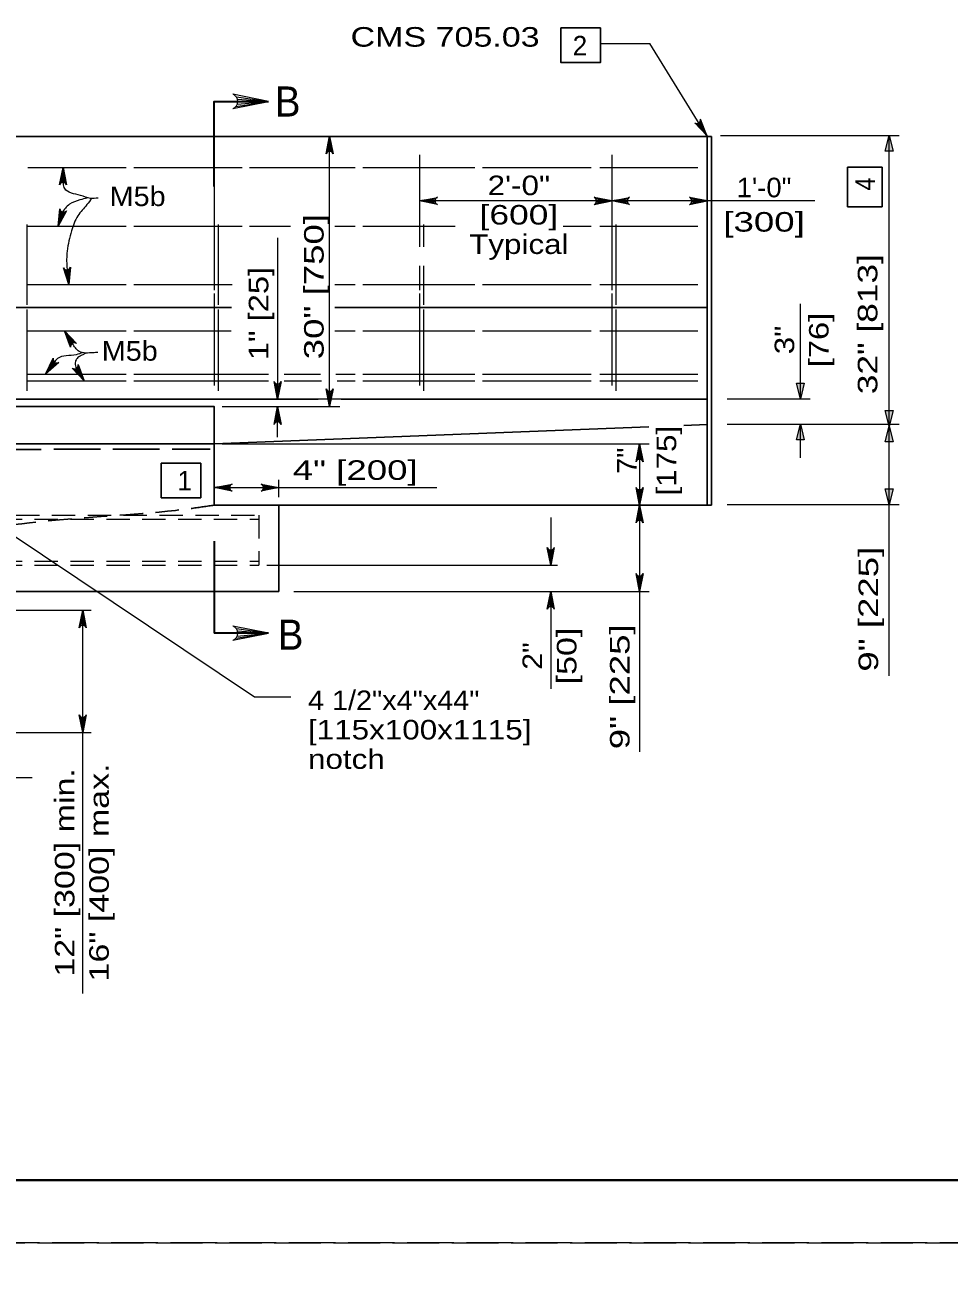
# Model space of a CAD drawing. Extents: x 1083.1 to 1123, y 697.4 to 741.4.
# Drawn here: x 1096.71 to 1104.08, y 719.1 to 729.07 of the extents above; entities that cross this region are included whole.
import ezdxf
from ezdxf.enums import TextEntityAlignment as Align

# ---------------------------------------------------------------- set-up
doc = ezdxf.new("R2010")
doc.units = 0
doc.header["$LTSCALE"] = 0.062
doc.linetypes.add('LONG_DASHED', pattern=[7.5, 6, -1.5])
doc.linetypes.add('MEDIUM_DASHED', pattern=[4.5, 3, -1.5])
doc.layers.add('1', color=7, linetype='Continuous', lineweight=13)

msp = doc.modelspace()

# ---------------------------------------------------------------- hatches: boundary and pattern name
at = {"layer": '1'}
for points in [[(1103.57467, 728.06383), (1103.60592, 728.18875), (1103.63717, 728.06383)], [(1102.92917, 726.21258), (1102.89792, 726.08758), (1102.86667, 726.21258)], [(1103.63717, 725.99342), (1103.60592, 725.8685), (1103.57467, 725.99342)], [(1102.86667, 725.76058), (1102.89792, 725.8855), (1102.92917, 725.76058)], [(1103.57467, 725.74358), (1103.60592, 725.8685), (1103.63717, 725.74358)], [(1103.63717, 725.36825), (1103.60592, 725.24333), (1103.57467, 725.36825)]]:
    msp.add_hatch(color=256, dxfattribs=at).paths.add_polyline_path(points)

# ---------------------------------------------------------------- linework, layer by layer
for p, q in [((1101.30292, 728.92225), (1101.69808, 728.92225)), ((1102.15483, 728.182), (1101.69808, 728.92225)), ((1098.4, 728.49667), (1098.65642, 728.46083)), ((1098.40867, 728.47892), (1098.65642, 728.46083)), ((1098.397, 728.42117), (1098.65642, 728.46083)), ((1098.40683, 728.43775), (1098.65642, 728.46083)), ((1098.41133, 728.46083), (1098.65642, 728.46083)), ((1102.06858, 728.2845), (1102.15267, 728.18875)), ((1102.078, 728.28475), (1102.15267, 728.18875)), ((1102.08858, 728.28892), (1102.15267, 728.18875)), ((1102.09533, 728.29475), (1102.15267, 728.18875)), ((1102.10033, 728.30292), (1102.15267, 728.18875)), ((1099.12417, 728.05458), (1099.144, 728.18433)), ((1099.1325, 728.0595), (1099.144, 728.18433)), ((1099.144, 726.02625), (1099.144, 728.18433)), ((1099.144, 728.06175), (1099.144, 728.18433)), ((1099.15308, 728.06042), (1099.144, 728.18433)), ((1099.16192, 728.05608), (1099.144, 728.18433)), ((1102.14325, 728.181), (1102.172, 728.181)), ((1102.172, 728.181), (1102.14325, 728.181)), ((1102.25975, 728.18875), (1103.68458, 728.18875)), ((1103.60592, 723.87792), (1103.60592, 728.18875)), ((1098.22375, 728.03392), (1098.22375, 726.95475)), ((1099.86175, 728.03392), (1099.86175, 727.29925)), ((1101.39433, 728.03392), (1101.39433, 726.95475)), ((1096.73733, 727.93217), (1097.52033, 727.93217)), ((1096.998, 727.80675), (1097.02008, 727.93217)), ((1097.00625, 727.81133), (1097.02008, 727.93217)), ((1097.01742, 727.81333), (1097.02008, 727.93217)), ((1097.02625, 727.81183), (1097.02008, 727.93217)), ((1097.03475, 727.80733), (1097.02008, 727.93217)), ((1097.58367, 727.93217), (1098.44517, 727.93217)), ((1098.50367, 727.93217), (1099.34775, 727.93217)), ((1099.40783, 727.93217), (1100.301, 727.93217)), ((1100.36275, 727.93217), (1101.22967, 727.93217)), ((1101.29775, 727.93217), (1102.07925, 727.93217)), ((1099.98992, 727.68508), (1099.86175, 727.66708)), ((1099.98558, 727.67617), (1099.86175, 727.66708)), ((1099.98425, 727.66708), (1099.86175, 727.66708)), ((1099.98658, 727.65558), (1099.86175, 727.66708)), ((1099.9915, 727.64733), (1099.86175, 727.66708)), ((1101.26467, 727.64733), (1101.39433, 727.66708)), ((1101.26617, 727.68508), (1101.39433, 727.66708)), ((1101.26958, 727.65558), (1101.39433, 727.66708)), ((1101.2705, 727.67617), (1101.39433, 727.66708)), ((1101.27183, 727.66708), (1101.39433, 727.66708)), ((1101.52258, 727.68508), (1101.39433, 727.66708)), ((1101.51825, 727.67617), (1101.39433, 727.66708)), ((1101.51692, 727.66708), (1101.39433, 727.66708)), ((1101.51917, 727.65558), (1101.39433, 727.66708)), ((1101.52408, 727.64733), (1101.39433, 727.66708)), ((1102.026, 727.64733), (1102.15567, 727.66708)), ((1102.0275, 727.68508), (1102.15567, 727.66708)), ((1102.03092, 727.65558), (1102.15567, 727.66708)), ((1102.03183, 727.67617), (1102.15567, 727.66708)), ((1102.03317, 727.66708), (1102.15567, 727.66708)), ((1096.99792, 727.589), (1096.97767, 727.465)), ((1097.00492, 727.58233), (1096.97767, 727.465)), ((1097.03333, 727.5795), (1096.97767, 727.465)), ((1097.01292, 727.57858), (1096.97767, 727.465)), ((1097.02425, 727.57733), (1096.97767, 727.465)), ((1096.728, 727.47933), (1096.728, 726.8375)), ((1098.25525, 727.47933), (1098.25525, 726.8375)), ((1099.89317, 727.47933), (1099.89317, 727.29925)), ((1101.42575, 727.47933), (1101.42575, 726.8375)), ((1096.73733, 727.465), (1097.52033, 727.465)), ((1097.58367, 727.465), (1098.44517, 727.465)), ((1098.50367, 727.465), (1098.83067, 727.465)), ((1098.72892, 727.371), (1098.72892, 726.08367)), ((1099.1855, 727.465), (1099.34775, 727.465)), ((1099.40783, 727.465), (1100.14475, 727.465)), ((1101.00675, 727.465), (1101.22967, 727.465)), ((1101.29775, 727.465), (1102.07925, 727.465)), ((1097.033, 727.12083), (1097.06483, 726.99933)), ((1097.04208, 727.11767), (1097.06483, 726.99933)), ((1097.05092, 727.11733), (1097.06483, 726.99933)), ((1097.06183, 727.12092), (1097.06483, 726.99933)), ((1097.06925, 727.12658), (1097.06483, 726.99933)), ((1099.86175, 727.149), (1099.86175, 726.95475)), ((1099.89317, 727.149), (1099.89317, 726.8375)), ((1096.73733, 726.99933), (1097.52033, 726.99933)), ((1097.58367, 726.99933), (1098.36642, 726.99933)), ((1099.1855, 726.99933), (1099.34775, 726.99933)), ((1099.40783, 726.99933), (1100.301, 726.99933)), ((1100.36275, 726.99933), (1101.22967, 726.99933)), ((1101.29775, 726.99933), (1102.07925, 726.99933)), ((1098.22375, 726.92725), (1098.22375, 726.19467)), ((1099.86175, 726.92725), (1099.86175, 726.19467)), ((1101.39433, 726.92725), (1101.39433, 726.19467)), ((1096.728, 726.80017), (1096.728, 726.1525)), ((1098.25525, 726.80017), (1098.25525, 726.1525)), ((1099.89317, 726.80017), (1099.89317, 726.1525)), ((1101.42575, 726.80017), (1101.42575, 726.1525)), ((1102.89792, 726.08758), (1102.89792, 726.84642)), ((1096.73733, 726.63092), (1097.52033, 726.63092)), ((1097.09183, 726.52983), (1097.02925, 726.63092)), ((1097.0835, 726.52208), (1097.02925, 726.63092)), ((1097.07917, 726.51375), (1097.02925, 726.63092)), ((1097.10008, 726.53342), (1097.02925, 726.63092)), ((1097.10958, 726.53433), (1097.02925, 726.63092)), ((1097.58367, 726.63092), (1098.35917, 726.63092)), ((1099.1855, 726.63092), (1099.34775, 726.63092)), ((1099.40783, 726.63092), (1100.301, 726.63092)), ((1100.36275, 726.63092), (1101.22967, 726.63092)), ((1101.29775, 726.63092), (1102.07925, 726.63092)), ((1096.94017, 726.3945), (1096.87875, 726.285)), ((1096.9445, 726.386), (1096.87875, 726.285)), ((1096.95075, 726.37967), (1096.87875, 726.285)), ((1096.961, 726.37458), (1096.87875, 726.285)), ((1096.97025, 726.3735), (1096.87875, 726.285)), ((1096.73733, 726.285), (1097.52033, 726.285)), ((1097.10633, 726.32667), (1097.1865, 726.22992)), ((1097.11583, 726.32758), (1097.1865, 726.22992)), ((1097.12408, 726.33108), (1097.1865, 726.22992)), ((1097.13242, 726.33883), (1097.1865, 726.22992)), ((1097.13675, 726.34708), (1097.1865, 726.22992)), ((1097.58367, 726.285), (1098.6565, 726.285)), ((1098.78033, 726.285), (1099.07183, 726.285)), ((1099.19258, 726.285), (1099.34775, 726.285)), ((1099.40783, 726.285), (1100.301, 726.285)), ((1100.36275, 726.285), (1101.22967, 726.285)), ((1101.29775, 726.285), (1102.07925, 726.285)), ((1096.73733, 726.22992), (1097.52033, 726.22992)), ((1097.58367, 726.22992), (1098.6565, 726.22992)), ((1098.711, 726.21183), (1098.72892, 726.08367)), ((1098.71992, 726.2075), (1098.72892, 726.08367)), ((1098.74875, 726.21333), (1098.72892, 726.08367)), ((1098.7405, 726.20842), (1098.72892, 726.08367)), ((1098.72892, 726.20617), (1098.72892, 726.08367)), ((1098.78033, 726.22992), (1099.07817, 726.22992)), ((1099.20525, 726.22992), (1099.34775, 726.22992)), ((1099.40783, 726.22992), (1100.301, 726.22992)), ((1100.36275, 726.22992), (1101.22967, 726.22992)), ((1101.29775, 726.22992), (1102.07925, 726.22992)), ((1102.09317, 726.08367), (1098.66642, 726.08367)), ((1099.12608, 726.15442), (1099.144, 726.02625)), ((1099.13492, 726.15008), (1099.144, 726.02625)), ((1099.16383, 726.15592), (1099.144, 726.02625)), ((1099.1555, 726.151), (1099.144, 726.02625)), ((1099.144, 726.14875), (1099.144, 726.02625)), ((1102.31508, 726.08758), (1102.97658, 726.08758)), ((1098.28625, 726.0255), (1099.22417, 726.0255)), ((1098.70908, 725.89575), (1098.72892, 726.0255)), ((1098.71742, 725.90067), (1098.72892, 726.0255)), ((1098.72892, 725.783), (1098.72892, 726.0255)), ((1098.72892, 725.90292), (1098.72892, 726.0255)), ((1098.738, 725.90158), (1098.72892, 726.0255)), ((1098.74692, 725.89725), (1098.72892, 726.0255)), ((1102.31508, 725.8855), (1103.68458, 725.8855)), ((1102.89792, 725.61592), (1102.89792, 725.8855)), ((1098.28625, 725.72725), (1101.69258, 725.72725)), ((1101.59567, 725.5975), (1101.6155, 725.72725)), ((1101.60392, 725.60242), (1101.6155, 725.72725)), ((1101.6155, 725.72725), (1101.6155, 725.23933)), ((1101.6155, 725.60467), (1101.6155, 725.72725)), ((1101.6245, 725.60342), (1101.6155, 725.72725)), ((1101.63342, 725.59908), (1101.6155, 725.72725)), ((1101.6155, 725.72725), (1101.6155, 724.55142)), ((1098.35192, 725.39708), (1098.22375, 725.37917)), ((1098.34758, 725.38825), (1098.22375, 725.37917)), ((1098.22375, 725.37917), (1099.999, 725.37917)), ((1098.34625, 725.37917), (1098.22375, 725.37917)), ((1098.3485, 725.36767), (1098.22375, 725.37917)), ((1098.35342, 725.35933), (1098.22375, 725.37917)), ((1098.60967, 725.399), (1098.73933, 725.37917)), ((1098.61117, 725.36125), (1098.73933, 725.37917)), ((1098.61458, 725.39067), (1098.73933, 725.37917)), ((1098.6155, 725.37008), (1098.73933, 725.37917)), ((1098.61683, 725.37917), (1098.73933, 725.37917)), ((1098.73933, 725.30183), (1098.73933, 725.44167)), ((1101.5975, 725.3675), (1101.6155, 725.23933)), ((1101.60642, 725.36317), (1101.6155, 725.23933)), ((1101.63525, 725.369), (1101.6155, 725.23933)), ((1101.627, 725.36408), (1101.6155, 725.23933)), ((1101.6155, 725.36183), (1101.6155, 725.23933)), ((1098.28625, 725.23933), (1100.97, 725.23933)), ((1101.59567, 725.10958), (1101.6155, 725.23933)), ((1101.60392, 725.1145), (1101.6155, 725.23933)), ((1101.6155, 725.23933), (1101.6155, 723.27167)), ((1101.6155, 725.11683), (1101.6155, 725.23933)), ((1101.6245, 725.1155), (1101.6155, 725.23933)), ((1101.63342, 725.11117), (1101.6155, 725.23933)), ((1102.31508, 725.24333), (1103.68458, 725.24333)), ((1100.9075, 725.13942), (1100.9075, 724.75958)), ((1100.8895, 724.88783), (1100.9075, 724.75958)), ((1100.89842, 724.88342), (1100.9075, 724.75958)), ((1100.92725, 724.88933), (1100.9075, 724.75958)), ((1100.919, 724.88442), (1100.9075, 724.75958)), ((1100.9075, 724.88217), (1100.9075, 724.75958)), ((1098.64192, 724.75958), (1100.96175, 724.75958)), ((1100.29208, 724.7595), (1100.29208, 724.75958)), ((1101.5975, 724.67967), (1101.6155, 724.55142)), ((1101.60642, 724.67533), (1101.6155, 724.55142)), ((1101.63525, 724.68117), (1101.6155, 724.55142)), ((1101.627, 724.67625), (1101.6155, 724.55142)), ((1101.6155, 724.674), (1101.6155, 724.55142)), ((1098.85717, 724.55142), (1101.69258, 724.55142)), ((1100.88767, 724.42175), (1100.9075, 724.55142)), ((1100.89592, 724.42667), (1100.9075, 724.55142)), ((1100.9075, 724.42892), (1100.9075, 724.55142)), ((1100.9165, 724.42758), (1100.9075, 724.55142)), ((1100.92542, 724.42325), (1100.9075, 724.55142)), ((1100.9075, 724.55142), (1100.9075, 723.77242)), ((1095.47167, 724.4025), (1097.24158, 724.4025)), ((1097.155, 724.27275), (1097.17483, 724.4025)), ((1097.16333, 724.27767), (1097.17483, 724.4025)), ((1097.17483, 721.34333), (1097.17483, 724.4025)), ((1097.17483, 724.27992), (1097.17483, 724.4025)), ((1097.18392, 724.27867), (1097.17483, 724.4025)), ((1097.19275, 724.27425), (1097.17483, 724.4025)), ((1098.397, 724.17842), (1098.65642, 724.21808)), ((1098.4, 724.25392), (1098.65642, 724.21808)), ((1098.40683, 724.19508), (1098.65642, 724.21808)), ((1098.40867, 724.23617), (1098.65642, 724.21808)), ((1098.41133, 724.21808), (1098.65642, 724.21808)), ((1097.15692, 723.55308), (1097.17483, 723.42492)), ((1097.16575, 723.54875), (1097.17483, 723.42492)), ((1097.19467, 723.55458), (1097.17483, 723.42492)), ((1097.18633, 723.54967), (1097.17483, 723.42492)), ((1097.17483, 723.54742), (1097.17483, 723.42492)), ((1095.459, 723.42492), (1097.24158, 723.42492)), ((1095.442, 723.06533), (1096.77125, 723.06533))]:
    msp.add_line(p, q, dxfattribs=at)
at = {"layer": '1', "lineweight": 25}
for p, q in [((1086.34158, 728.181), (1102.15567, 728.181)), ((1102.14, 728.181), (1102.16883, 728.181)), ((1102.18992, 728.181), (1102.15567, 728.181)), ((1102.15567, 727.148), (1102.15567, 728.181)), ((1102.18992, 727.09258), (1102.18992, 728.181)), ((1102.15567, 725.23933), (1102.15567, 727.148)), ((1102.18992, 725.23933), (1102.18992, 727.09258)), ((1090.9565, 726.81608), (1098.36008, 726.81608)), ((1099.1855, 726.81608), (1102.15567, 726.81608)), ((1086.37042, 726.08367), (1099.05267, 726.08367)), ((1099.23567, 726.08367), (1102.15567, 726.08367)), ((1102.15567, 725.88158), (1101.96825, 725.87425)), ((1101.68917, 725.86325), (1098.22375, 725.72725)), ((1098.22375, 725.72725), (1095.52742, 725.72725)), ((1098.73933, 724.55142), (1098.73933, 725.23933)), ((1095.96625, 724.55142), (1098.73933, 724.55142))]:
    msp.add_line(p, q, dxfattribs=at)
at = {"layer": '1', "linetype": 'LONG_DASHED', "lineweight": 25}
msp.add_line((1095.52742, 725.68342), (1098.19225, 725.68575), dxfattribs=at)
at = {"layer": '1', "linetype": 'MEDIUM_DASHED'}
for p, q in [((1089.92717, 725.12742), (1098.57942, 725.12742)), ((1098.57942, 725.15933), (1098.57942, 724.75958)), ((1089.92717, 724.79158), (1098.57942, 724.79158)), ((1089.92717, 724.75958), (1098.57942, 724.75958))]:
    msp.add_line(p, q, dxfattribs=at)
at = {"layer": '1', "lineweight": 35}
for p in [(1098.22375, 724.95125), (1098.65642, 724.21808)]:
    msp.add_line(p, (1098.22375, 724.21808), dxfattribs=at)
at = {"layer": '1', "linetype": 'LONG_DASHED'}
for points in [[(1083.12642, 719.35408), (1117.12642, 719.35408), (1117.12642, 741.35408), (1083.12642, 741.35408)], [(1083.12642, 697.35408), (1117.12642, 697.35408), (1117.12642, 719.35408), (1083.12642, 719.35408)]]:
    msp.add_lwpolyline(points, close=True, dxfattribs=at)
at = {"layer": '1', "lineweight": 25}
for points in [[(1116.62642, 719.85408), (1085.12642, 719.85408), (1085.12642, 740.85408)], [(1098.22375, 725.23933), (1098.22375, 726.0255), (1090.30608, 726.0255)], [(1102.18992, 725.23933), (1102.15567, 725.23933), (1098.22375, 725.23933)]]:
    msp.add_lwpolyline(points, dxfattribs=at)
at = {"layer": '1', "lineweight": 40}
msp.add_lwpolyline([(1085.12642, 740.85408), (1116.62642, 740.85408), (1116.62642, 719.85408), (1085.12642, 719.85408)], close=True, dxfattribs=at)
at = {"layer": '1', "lineweight": 25}
for points in [[(1100.98858, 729.04667), (1100.98858, 728.77117), (1101.30292, 728.77117), (1101.30292, 729.04667)], [(1103.2745, 727.62067), (1103.54992, 727.62067), (1103.54992, 727.935), (1103.2745, 727.935)], [(1097.80125, 725.57358), (1097.80125, 725.29825), (1098.11567, 725.29825), (1098.11567, 725.57358)]]:
    msp.add_lwpolyline(points, close=True, dxfattribs=at)
at = {"layer": '1'}
for points in [[(1098.37317, 728.40417), (1098.65642, 728.46083), (1098.37317, 728.51742)], [(1102.0555, 728.28975), (1102.15267, 728.18875), (1102.10183, 728.31933)], [(1099.11567, 728.04267), (1099.144, 728.18433), (1099.17233, 728.04267)], [(1096.98958, 727.79542), (1097.02008, 727.93217), (1097.04458, 727.79417)], [(1100.00333, 727.63883), (1099.86175, 727.66708), (1100.00333, 727.69542)], [(1103.01383, 727.66708), (1101.39433, 727.66708), (1099.86175, 727.66708)], [(1101.25275, 727.63883), (1101.39433, 727.66708), (1101.25275, 727.69542)], [(1101.536, 727.63883), (1101.39433, 727.66708), (1101.536, 727.69542)], [(1102.01408, 727.63883), (1102.15567, 727.66708), (1102.01408, 727.69542)], [(1097.04458, 727.58808), (1096.97767, 727.465), (1096.99208, 727.60433)], [(1097.07608, 727.139), (1097.06483, 726.99933), (1097.0215, 727.13258)], [(1097.07825, 726.49967), (1097.02925, 726.63092), (1097.125, 726.52858)], [(1096.98383, 726.37775), (1096.87875, 726.285), (1096.94008, 726.411)], [(1097.13767, 726.36125), (1097.1865, 726.22992), (1097.09092, 726.33242)], [(1098.75725, 726.22525), (1098.72892, 726.08367), (1098.70067, 726.22525)], [(1099.17233, 726.16783), (1099.144, 726.02625), (1099.11567, 726.16783)], [(1098.70067, 725.88383), (1098.72892, 726.0255), (1098.75725, 725.88383)], [(1101.58717, 725.58567), (1101.6155, 725.72725), (1101.64375, 725.58567)], [(1095.72475, 725.59842), (1098.545, 723.711), (1098.8335, 723.711)], [(1098.36533, 725.35083), (1098.22375, 725.37917), (1098.36533, 725.4075)], [(1098.59775, 725.4075), (1098.73933, 725.37917), (1098.59775, 725.35083)], [(1101.64375, 725.38092), (1101.6155, 725.23933), (1101.58717, 725.38092)], [(1101.58717, 725.09775), (1101.6155, 725.23933), (1101.64375, 725.09775)], [(1100.93575, 724.90117), (1100.9075, 724.75958), (1100.87917, 724.90117)], [(1101.64375, 724.69308), (1101.6155, 724.55142), (1101.58717, 724.69308)], [(1100.87917, 724.40983), (1100.9075, 724.55142), (1100.93575, 724.40983)], [(1097.1465, 724.26092), (1097.17483, 724.4025), (1097.20317, 724.26092)], [(1098.37317, 724.16142), (1098.65642, 724.21808), (1098.37317, 724.27475)], [(1097.20317, 723.5665), (1097.17483, 723.42492), (1097.1465, 723.5665)]]:
    msp.add_lwpolyline(points, dxfattribs=at)
at = {"layer": '1', "lineweight": 35}
msp.add_lwpolyline([(1098.22375, 727.78117), (1098.22375, 728.46083), (1098.65642, 728.46083)], dxfattribs=at)
at = {"layer": '1'}
for points in [[(1103.57467, 728.06383), (1103.60592, 728.18875), (1103.63717, 728.06383)], [(1102.92917, 726.21258), (1102.89792, 726.08758), (1102.86667, 726.21258)], [(1103.63717, 725.99342), (1103.60592, 725.8685), (1103.57467, 725.99342)], [(1102.86667, 725.76058), (1102.89792, 725.8855), (1102.92917, 725.76058)], [(1103.57467, 725.74358), (1103.60592, 725.8685), (1103.63717, 725.74358)], [(1103.63717, 725.36825), (1103.60592, 725.24333), (1103.57467, 725.36825)]]:
    msp.add_lwpolyline(points, close=True, dxfattribs=at)
at = {"layer": '1', "linetype": 'MEDIUM_DASHED'}
msp.add_lwpolyline([(1089.92717, 725.15933), (1092.067, 725.15933), (1098.57942, 725.15933)], dxfattribs=at)
at = {"layer": '1'}
for centre, radius, start, end in [((1098.35032, 728.46086), 0.06112, 292.08605, 67.91218), ((1099.14404, 728.03126), 0.03056, 22.08782, 157.91395), ((1100.01479, 727.66715), 0.03056, 112.08782, 247.91395), ((1101.24133, 727.66715), 0.03056, 292.08605, 67.91218), ((1101.54741, 727.66715), 0.03056, 112.08782, 247.91395), ((1102.00264, 727.66715), 0.03056, 292.08605, 67.91218), ((1098.72892, 726.23667), 0.03056, 202.08782, 337.91395), ((1099.14398, 726.17924), 0.03056, 202.08782, 337.91395), ((1098.72898, 725.87243), 0.03056, 22.08782, 157.91395), ((1101.6155, 725.5742), 0.03056, 22.08782, 157.91395), ((1098.37676, 725.37921), 0.03056, 112.08782, 247.91395), ((1098.58632, 725.37914), 0.03056, 292.08782, 67.91395), ((1101.61543, 725.39236), 0.03056, 202.08782, 337.91395), ((1101.6155, 725.08628), 0.03056, 22.08782, 157.91395), ((1100.90743, 724.91263), 0.03056, 202.08782, 337.91395), ((1101.61543, 724.70448), 0.03056, 202.08782, 337.91395), ((1100.90749, 724.39841), 0.03056, 22.08782, 157.91395), ((1097.17487, 724.24945), 0.03056, 22.08782, 157.91395), ((1098.35032, 724.21814), 0.06112, 292.08605, 67.91218), ((1097.1748, 723.57794), 0.03056, 202.08782, 337.91395)]:
    msp.add_arc(centre, radius, start, end, dxfattribs=at)
for centre, major_axis, start_param, end_param in [((1102.07265, 728.31394), (0.0263, 0.01371), 3.6150116, 5.9856247), ((1097.0168, 727.78363), (0.02966, 0), 0.3633246, 2.7339377), ((1097.02169, 727.60687), (-0.02966, 0), 0.084585, 2.4551981), ((1097.04746, 727.14686), (-0.02966, 0), 0.5029452, 2.8735583), ((1097.1075, 726.50464), (0.02966, 0), 0.940338, 3.3109511), ((1096.9687, 726.40325), (-0.02966, 0), 6.0185309, 8.389144), ((1097.10846, 726.35633), (-0.02966, 0), 0.9383465, 3.3089596)]:
    msp.add_ellipse(centre, major_axis=major_axis, ratio=0.999895, start_param=start_param, end_param=end_param, dxfattribs=at)
for points in [[(1097.29833, 727.68975), (1097.23692, 727.68692), (1097.15675, 727.7105), (1097.03158, 727.76608), (1097.02067, 727.80575), (1097.01833, 727.85408), (1097.02008, 727.93217)], [(1097.21117, 727.69), (1097.152, 727.67508), (1097.0695, 727.63967), (1097.01067, 727.57125), (1096.97767, 727.465)], [(1097.24642, 727.68742), (1097.20858, 727.63733), (1097.13558, 727.54767), (1097.08608, 727.42725), (1097.05067, 727.26675), (1097.04833, 727.13933), (1097.06483, 726.99933)], [(1097.29475, 726.45758), (1097.25717, 726.45525), (1097.14667, 726.46583), (1097.0915, 726.5305), (1097.02925, 726.63092)], [(1097.17325, 726.45592), (1097.12317, 726.43992), (1096.974, 726.40933), (1096.91875, 726.33758), (1096.87875, 726.285)], [(1097.20233, 726.45242), (1097.18858, 726.44533), (1097.162, 726.43242), (1097.12967, 726.41008), (1097.116, 726.38483), (1097.11883, 726.3395), (1097.1865, 726.22992)]]:
    msp.add_spline(points, degree=3, dxfattribs=at)
at = {"layer": '1', "linetype": 'MEDIUM_DASHED', "lineweight": 25}
msp.add_spline([(1098.22375, 725.23933), (1098.04758, 725.21383), (1096.98908, 725.12192), (1096.03667, 725.0285), (1095.57642, 724.98017), (1095.5285, 724.96108), (1095.50342, 724.92958), (1095.47667, 724.89208), (1095.44192, 724.84092)], degree=3, dxfattribs=at)

# ---------------------------------------------------------------- texts
at = {"layer": '1'}
for s, height, width, p in [('CMS 705.03', 0.156, 1.3, (1099.311, 728.89775)), ('B', 0.24, 0.95, (1098.708, 728.34008)), ('M5b', 0.156, 1.1, (1097.38942, 727.62558)), ('M5b', 0.156, 1.1, (1097.32658, 726.39175)), ('4" [200]', 0.156, 1.4, (1098.84917, 725.441)), ('B', 0.24, 0.95, (1098.731, 724.08558)), ('4 1/2"x4"x44"', 0.156, 1.1, (1098.9715, 723.60417)), ('[115x100x1115]', 0.156, 1.2, (1098.9715, 723.3695)), ('notch', 0.156, 1.2, (1098.9715, 723.13483))]:
    msp.add_text(s, height=height, dxfattribs=dict(at, width=width)).set_placement(p)
for s, p in [('2', (1101.08192, 728.82767)), ('1', (1097.92992, 725.35625))]:
    msp.add_text(s, height=0.156, dxfattribs=at).set_placement(p)
for s, width, p in [('2\'-0"', 1.2, (1100.65304, 727.71283)), ('1\'-0"', 1.05, (1102.60838, 727.69583)), ('[600]', 1.35, (1100.65313, 727.47817)), ('[300]', 1.4, (1102.60842, 727.42183)), ('Typical', 1.2, (1100.65308, 727.2435))]:
    msp.add_text(s, height=0.156, dxfattribs=dict(at, width=width)).set_placement(p, align=Align.CENTER)
for s, width, p in [('4', 0.9, (1103.49192, 727.74925)), ('30" [750]', 1.4, (1099.09617, 726.40317)), ('32" [813]', 1.35, (1103.51183, 726.12458)), ('1" [25]', 1.25, (1098.65492, 726.3955)), ('9" [225]', 1.4, (1103.518, 723.9105)), ('9" [225]', 1.4, (1101.53575, 723.29142))]:
    msp.add_text(s, height=0.156, rotation=90, dxfattribs=dict(at, width=width)).set_placement(p)
for s, width, p in [('[76]', 1.25, (1103.12292, 726.55717)), ('3"', 1.2, (1102.84892, 726.55721)), ('[175]', 1.2, (1101.908, 725.59404)), ('7"', 1.1, (1101.592, 725.59404)), ('[50]', 1.3, (1101.112, 724.03546)), ('2"', 1.15, (1100.838, 724.03546)), ('12" [300] min.', 1.3, (1097.10858, 722.30837)), ('16" [400] max.', 1.3, (1097.38258, 722.30833))]:
    msp.add_text(s, height=0.156, rotation=90, dxfattribs=dict(at, width=width)).set_placement(p, align=Align.CENTER)

doc.saveas('drawing.dxf')
